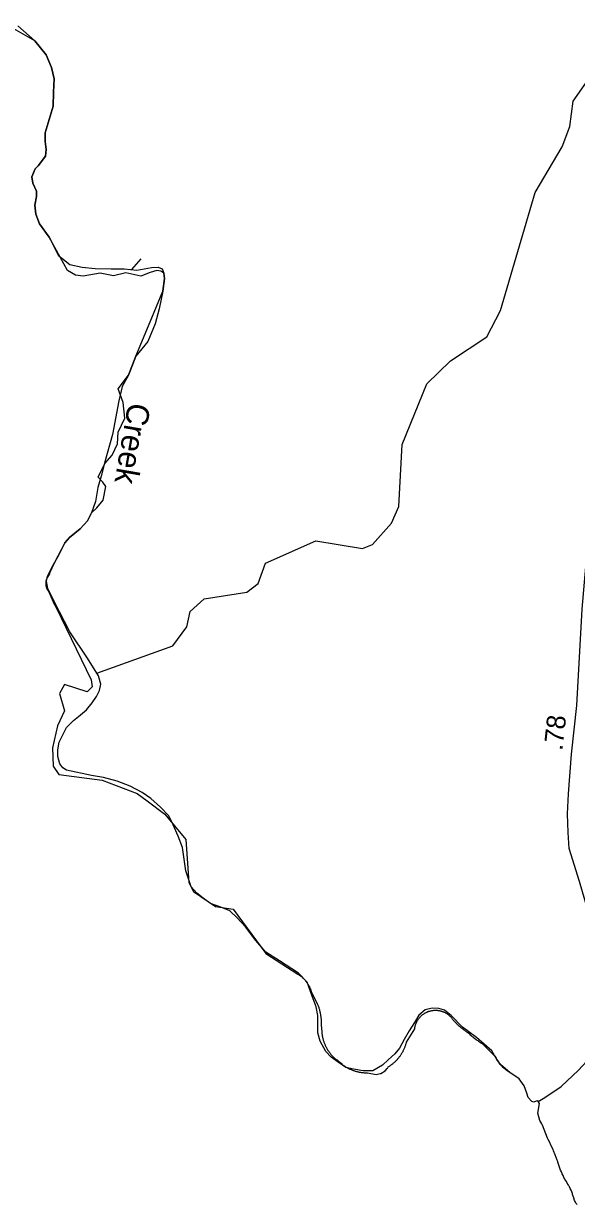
# Model space of a CAD drawing. Extents: x 2220236 to 2384410, y 720751 to 894131.
# Drawn here: x 2232586 to 2236238, y 720823 to 728622 of the extents above; entities that cross this region are included whole.
import ezdxf

# ---------------------------------------------------------------- set-up
doc = ezdxf.new("R2010")
doc.units = 0
doc.layers.add('Default', color=7, linetype='Continuous')

msp = doc.modelspace()

# ---------------------------------------------------------------- linework, layer by layer
at = {"layer": 'Default'}
for points in [[(2232770.3, 728332.6), (2232734.2, 728415.9), (2232659.3, 728507.6), (2232460.8, 728621.8)], [(2232548.3, 728607.6), (2232659.3, 728507.6), (2232734.2, 728415.9), (2232770.3, 728332.6), (2232787, 728257.6), (2232784.2, 728168.7), (2232781.4, 728077.1), (2232748.1, 727966), (2232728.7, 727899.3), (2232728.7, 727843.8), (2232735.6, 727791), (2232730.1, 727746.6), (2232682.9, 727682.7), (2232663.5, 727663.3), (2232641.3, 727610.5), (2232646.8, 727568.8), (2232671.8, 727516), (2232671.8, 727479.9), (2232660.7, 727421.6), (2232666.2, 727363.3), (2232691.2, 727299.4), (2232755.1, 727210.5), (2232816.1, 727091.1), (2232891.1, 727030), (2232973, 727013.3), (2233059, 727005), (2233164.5, 727002.2), (2233250.5, 727002.2), (2233333.8, 726993.9), (2233431, 727010.6), (2233475.4, 727013.3), (2233500.4, 727002.2), (2233511.5, 726974.4), (2233517, 726938.3), (2233505.9, 726855), (2233480.9, 726738.4), (2233456, 726638.4), (2233406, 726521.7), (2233326.9, 726424.5), (2233279.7, 726299.5), (2233238.1, 726224.5), (2233215.8, 726130.1), (2233174.2, 725907.9), (2233122.9, 725727.4), (2233097.9, 725632.9), (2233075.7, 725558), (2233061.8, 725466.3), (2233034, 725391.3), (2233009.1, 725338.5), (2232959.1, 725285.8), (2232889.7, 725227.4), (2232859.2, 725191.3)], [(2233068.9, 724331.3), (2233572.2, 724512.2), (2233663.3, 724638.2), (2233687.3, 724739.4), (2233778.3, 724822.9), (2234061.3, 724866.3), (2234135.3, 724923.8), (2234184.3, 725057.3), (2234516.3, 725204.6), (2234825.3, 725155.6), (2234891.4, 725180.6), (2235015.2, 725322.3), (2235064.2, 725432.9), (2235086.4, 725842.4), (2235249.2, 726242.5), (2235406.3, 726393.5), (2235646.4, 726552.5), (2235737.2, 726727.8), (2235964.2, 727507.1), (2236144.2, 727808.4), (2236193.3, 727941.9), (2236217.2, 728108.7), (2236439.3, 728425.5)], [(2232859.2, 725191.3), (2232889.7, 725227.4), (2232959.1, 725285.8), (2233009.1, 725338.5), (2233034, 725391.3), (2233070.2, 725422.5), (2233110.9, 725474), (2233130.2, 725564.1), (2233108.8, 725594.1), (2233078.8, 725626.3), (2233121.7, 725716.4), (2233171, 725772.2), (2233205.3, 725845.2), (2233211.8, 725922.4), (2233254.7, 726016.8), (2233244, 726119.8), (2233211.8, 726210), (2233279.7, 726299.5), (2233326.9, 726424.5), (2233422.1, 726652), (2233505.9, 726855), (2233517, 726938.3), (2233511.5, 726974.5), (2233492.9, 726986.7), (2233467.1, 726991), (2233422.1, 726978.1), (2233359.8, 726954.5), (2233261.1, 726976), (2233179.6, 726956.7), (2233091.6, 726973.8), (2232980, 726954.5), (2232928.5, 726961), (2232877.1, 726991), (2232755.1, 727210.5), (2232691.2, 727299.4), (2232666.2, 727363.3), (2232660.7, 727421.6), (2232671.8, 727479.9), (2232671.8, 727516.1), (2232646.8, 727568.8), (2232641.3, 727610.5), (2232663.5, 727663.3), (2232682.9, 727682.7), (2232730.1, 727746.6), (2232735.6, 727791), (2232728.7, 727843.8), (2232728.7, 727899.3), (2232748.1, 727966), (2232781.4, 728077.1), (2232784.2, 728168.8), (2232787, 728257.6), (2232770.3, 728332.6)], [(2233360.2, 727068.4), (2233299.2, 726997.4)], [(2235984.8, 721503.1), (2236028.2, 721528.7), (2236136.5, 721602), (2236250.8, 721708.4), (2236306.4, 721768.9), (2236361.7, 721839.3), (2236409, 721927.5), (2236442.2, 722021.8), (2236451.6, 722099.8), (2236456.9, 722193.9), (2236425.5, 722367.4), (2236349.1, 722644.7), (2236257.5, 722956.3), (2236190.6, 723173), (2236182.2, 723279.2), (2236179.1, 723403), (2236186, 723535), (2236205.8, 723797.1), (2236241.3, 724117.1), (2236276.6, 724753.6), (2236311.7, 725161.5), (2236343.5, 725365.5)], [(2232859.2, 725191.3), (2232788.9, 725058.6), (2232760.1, 724997.5), (2232755.3, 724980.6), (2232753.5, 724978.7), (2232751.9, 724976.8), (2232750.2, 724974.8), (2232748.8, 724972.8), (2232747.3, 724970.8), (2232745.7, 724968.6), (2232744.3, 724966.5), (2232743, 724964.3), (2232741.8, 724962.1), (2232740.6, 724959.7), (2232739.5, 724957.5), (2232738.5, 724955.1), (2232737.5, 724952.8), (2232736.7, 724950.4), (2232736.1, 724948), (2232735.2, 724945.5), (2232734.4, 724943), (2232734, 724940.6), (2232733.6, 724938), (2232733, 724935.5), (2232732.8, 724933), (2232732.6, 724930.4), (2232732.2, 724927.9), (2232732.2, 724925.3), (2232732.2, 724922.8), (2232732.2, 724920.3), (2232732.2, 724917.7), (2232732.6, 724915.1), (2232732.8, 724912.6), (2232733.2, 724910.1), (2232733.8, 724907.6), (2232734.2, 724905), (2232734.8, 724902.6), (2232735.4, 724900.1), (2232736.3, 724897.7), (2232737.3, 724895.3), (2232737.9, 724892.9), (2232738.9, 724890.5), (2232740.2, 724888.2), (2232741.2, 724885.9), (2232742.4, 724883.7), (2232743.6, 724881.5), (2232745.1, 724879.3), (2232746.5, 724877.2), (2232748, 724875.1), (2232749.6, 724873.1), (2232780.8, 724801.6), (2232783.4, 724796.6), (2232801.1, 724764.4), (2233032.8, 724288.2), (2233039.5, 724241.1), (2233006.5, 724208.1), (2232855.8, 724257), (2232823.8, 724196.8), (2232857, 724081.8), (2232810.1, 723983.1), (2232777.5, 723838.4), (2232780.6, 723718.1), (2232819.5, 723662.2), (2233105.8, 723624.4), (2233335.8, 723537.8), (2233401.3, 723489.3), (2233519.6, 723400.4), (2233658.2, 723233.1), (2233678.1, 722948.1), (2233708.4, 722890.3), (2233853.8, 722790.5), (2233969.4, 722773.7), (2234185.2, 722479), (2234397.8, 722343.6), (2234401.1, 722341.6), (2234404.2, 722339.4), (2234407.4, 722337.2), (2234410.7, 722335), (2234414, 722332.7), (2234417.3, 722330.3), (2234420.2, 722328), (2234423.2, 722325.4), (2234426.3, 722322.9)], [(2235989.9, 721497), (2235982, 721507.3), (2235971.8, 721505.7), (2235956.8, 721497), (2235943.9, 721502.7), (2235918.9, 721529.5), (2235910, 721558.1), (2235892.1, 721606.4), (2235860, 721652.8), (2235797.4, 721693.9), (2235736.7, 721747.6), (2235712.7, 721780.6), (2235679.4, 721836.2), (2235576.7, 721925.1), (2235485.1, 721994.5), (2235410.1, 722069.5), (2235365.7, 722105.6), (2235329.6, 722116.7), (2235285.2, 722119.5), (2235238, 722108.4), (2235196.4, 722072.3), (2235168.6, 722025.1), (2235132.5, 721969.5), (2235099.2, 721911.2), (2235068.7, 721855.6), (2235038.2, 721816.8), (2234993.7, 721777.9), (2234957.7, 721741.8), (2234892.4, 721705.7), (2234828.6, 721705.7), (2234764.7, 721716.8), (2234714.8, 721727.9), (2234664.8, 721761.2), (2234617.6, 721794.5), (2234581.5, 721833.4), (2234545.5, 721900.1), (2234528.8, 721955.6), (2234528.8, 722011.2), (2234528.8, 722069.5), (2234517.7, 722127.8), (2234492.7, 722197.3), (2234459.4, 722291.7), (2234401.1, 722350), (2234276.2, 722430.6), (2234186, 722488.9), (2234119.4, 722566.7), (2234052.7, 722655.5), (2233997.2, 722716.6), (2233947.3, 722761.1), (2233889, 722786.1), (2233819.6, 722811.1), (2233772.4, 722844.4), (2233730.8, 722877.7), (2233691.9, 722919.4), (2233675.2, 722972.2), (2233657.2, 723024.9), (2233635, 723180.5), (2233607.2, 723255.5), (2233573.9, 723330.5), (2233546.2, 723388.8), (2233490.7, 723447.1), (2233426.8, 723502.7), (2233368.5, 723544.3), (2233290.8, 723586), (2233204.7, 723619.3), (2233113.1, 723641.5), (2233035.4, 723655.4), (2232870.3, 723691.5), (2232845.3, 723705.4), (2232825.9, 723733.2), (2232812, 723780.4), (2232812, 723824.8), (2232820.3, 723874.8), (2232845.3, 723924.8), (2232870.3, 723972), (2232914.7, 724019.3), (2232948, 724044.3), (2233000.7, 724088.7), (2233039.6, 724135.9), (2233067.3, 724177.6), (2233086.8, 724216.5), (2233096.5, 724258.1), (2233079.8, 724313.7), (2233007.7, 724430.3), (2232891.1, 724605.3), (2232788.4, 724805.3), (2232746.7, 724891.4), (2232738.4, 724938.6), (2232744, 724971.9), (2232771.7, 725030.2), (2232823.1, 725119.1), (2232859.2, 725191.3)], [(2234426.3, 722322.9), (2234429.2, 722320.3), (2234432, 722317.5), (2234434.9, 722314.9), (2234437.8, 722312.1), (2234440.5, 722309.2), (2234442.9, 722306.4), (2234445.8, 722303.4), (2234448.2, 722300.4), (2234450.7, 722297.4), (2234453.2, 722294.3), (2234455.4, 722291.2), (2234457.7, 722288), (2234459.9, 722284.7), (2234462.2, 722281.5), (2234464.2, 722278.1), (2234466.3, 722274.8), (2234468.3, 722271.4), (2234470.2, 722267.9), (2234472, 722264.5), (2234473.7, 722261), (2234475.5, 722257.4), (2234477.2, 722253.9), (2234478.8, 722250.2), (2234480.2, 722246.6), (2234481.7, 722243), (2234482.9, 722239.3), (2234484.3, 722235.5), (2234485.6, 722231.8), (2234486.6, 722228), (2234528, 722143.8), (2234530.1, 722138.9), (2234531.7, 722134), (2234533.5, 722129.1), (2234535.2, 722124.2), (2234536.8, 722119.3), (2234538.3, 722114.3), (2234539.7, 722109.3), (2234540.9, 722104.3), (2234542.2, 722099.3), (2234543.6, 722094.2), (2234544.4, 722089.1), (2234545.4, 722084), (2234546.5, 722078.9), (2234547.5, 722073.8), (2234548.3, 722068.7), (2234548.9, 722063.5), (2234549.5, 722058.4), (2234550, 722053.2), (2234550.6, 722048.1), (2234551, 722042.9), (2234551.2, 722037.7), (2234551.6, 722032.5), (2234551.6, 722027.3), (2234551.6, 722022.1), (2234551.6, 722016.9), (2234551.6, 722011.8), (2234552.4, 722001.3), (2234553.2, 721990.9), (2234554.3, 721980.4), (2234555.1, 721969.9), (2234555.7, 721959.4), (2234556.5, 721948.9), (2234557.3, 721944.3), (2234557.9, 721939.7), (2234558.8, 721935.2), (2234559.8, 721930.6), (2234560.8, 721926), (2234562, 721921.5), (2234563.1, 721917), (2234564.3, 721912.5), (2234565.7, 721908), (2234567, 721903.5), (2234568.4, 721899.1), (2234570, 721894.7), (2234571.7, 721890.4), (2234573.5, 721886), (2234575.2, 721881.7), (2234577, 721877.5), (2234579.1, 721873.2), (2234580.9, 721868.9), (2234583, 721864.7), (2234585.2, 721860.6), (2234587.3, 721856.5), (2234589.5, 721852.4), (2234592, 721848.4), (2234594.2, 721844.4), (2234596.7, 721840.4), (2234599.2, 721836.5), (2234602, 721832.6), (2234604.5, 721828.8)], [(2235028.3, 721755.2), (2235031.8, 721758.3), (2235035.3, 721761.3), (2235038.6, 721764.4), (2235042.1, 721767.6), (2235045.2, 721770.9), (2235048.4, 721774.2), (2235051.7, 721777.5), (2235054.8, 721780.9), (2235058.1, 721784.4), (2235060.9, 721787.9), (2235064, 721791.5), (2235066.7, 721795.1), (2235069.8, 721798.8), (2235072.4, 721802.5), (2235075.1, 721806.2), (2235077.8, 721810), (2235080.2, 721813.9), (2235082.7, 721817.8), (2235085.3, 721821.7), (2235087.8, 721825.7), (2235090.1, 721829.7), (2235092.3, 721833.8), (2235094.2, 721837.9), (2235096.4, 721842.1), (2235098.5, 721846.2), (2235100.5, 721850.4), (2235102.2, 721854.6), (2235104, 721858.9), (2235105.8, 721863.2), (2235107.5, 721867.6), (2235108.9, 721871.9), (2235110.6, 721876.3), (2235112, 721880.7), (2235113.4, 721885.1), (2235114.7, 721889.6), (2235116.1, 721894.1), (2235169.4, 721983.1), (2235170, 721986.4), (2235170.4, 721989.6), (2235171.1, 721992.9), (2235171.7, 721996.2), (2235172.5, 721999.5), (2235173.3, 722002.7), (2235174.3, 722005.9), (2235175.2, 722009), (2235176.2, 722012.3), (2235177.4, 722015.3), (2235178.4, 722018.5), (2235179.7, 722021.6), (2235181.3, 722024.6), (2235182.7, 722027.6), (2235184.2, 722030.6), (2235185.8, 722033.5), (2235187.3, 722036.4), (2235189.1, 722039.3), (2235190.7, 722042.1), (2235192.8, 722044.9), (2235194.4, 722047.6), (2235196.5, 722050.3), (2235198.5, 722052.9), (2235200.8, 722055.5), (2235203, 722058.1), (2235205.1, 722060.5), (2235207.6, 722062.9), (2235209.8, 722065.3), (2235212.3, 722067.6), (2235214.5, 722069.9), (2235217, 722072), (2235219.7, 722074.3), (2235222.3, 722076.3), (2235225, 722078.3), (2235227.6, 722080.2), (2235230.5, 722082.1), (2235233.2, 722083.9), (2235236.1, 722085.7), (2235238.9, 722087.4), (2235241.8, 722088.9), (2235244.7, 722090.5), (2235247.7, 722091.9), (2235250.8, 722093.3), (2235254.1, 722094.7), (2235257, 722095.9), (2235260, 722097.1), (2235263.3, 722098.2), (2235266.4, 722099.2), (2235269.5, 722100.1), (2235272.8, 722101), (2235276, 722101.7), (2235279.3, 722102.4), (2235282.4, 722103.1), (2235286.1, 722103.6), (2235289.2, 722104.1), (2235292.4, 722104.5), (2235295.7, 722104.8), (2235299.2, 722105.1), (2235302.5, 722105.2), (2235305.8, 722105.3), (2235309.3, 722105.3), (2235312.5, 722105.1)], [(2235312.5, 722105.1), (2235315.8, 722105), (2235319.1, 722104.8), (2235322.6, 722104.4), (2235325.7, 722104), (2235328.9, 722103.5), (2235332.2, 722103), (2235335.5, 722102.3), (2235338.8, 722101.6), (2235342.1, 722100.8), (2235345.3, 722099.9), (2235348.4, 722098.9), (2235351.7, 722097.9), (2235354.8, 722096.8), (2235358.1, 722095.6), (2235360.9, 722094.3), (2235364, 722093), (2235367.1, 722091.6), (2235370, 722090), (2235373, 722088.5), (2235375.9, 722086.9), (2235378.8, 722085.2), (2235381.4, 722083.4), (2235384.5, 722081.6), (2235387.2, 722079.7), (2235389.8, 722077.7), (2235392.5, 722075.7), (2235395, 722073.6), (2235397.4, 722071.5), (2235400.1, 722069.2), (2235402.6, 722067), (2235405, 722064.7), (2235407.3, 722062.3), (2235410.6, 722057.8), (2235414, 722053.4), (2235417.3, 722049), (2235420.8, 722044.7), (2235424.3, 722040.4), (2235428, 722036.2), (2235431.5, 722032), (2235435.2, 722028), (2235439.1, 722023.8), (2235443, 722019.8), (2235446.8, 722015.9), (2235450.7, 722012), (2235454.8, 722008.1), (2235458.7, 722004.4), (2235463, 722000.6), (2235466.9, 721996.9), (2235471.3, 721993.4), (2235475.6, 721989.8), (2235480.1, 721986.3), (2235484.2, 721982.9), (2235488.7, 721979.6), (2235493.2, 721976.2), (2235497.7, 721973), (2235502.2, 721969.8), (2235506.7, 721966.8), (2235511.4, 721963.7), (2235516.2, 721960.8), (2235520.7, 721957.8), (2235526, 721953.1), (2235531.3, 721948.3), (2235536.5, 721943.6), (2235541.8, 721939), (2235547.3, 721934.5), (2235552.5, 721930), (2235558, 721925.5), (2235563.5, 721921.2), (2235569.3, 721916.9), (2235574.8, 721912.7), (2235580.5, 721908.5), (2235586.3, 721904.4), (2235592, 721900.4), (2235597.8, 721896.4), (2235603.7, 721892.5), (2235609.5, 721888.7), (2235615.4, 721884.9), (2235642.1, 721858.9), (2235668.3, 721832.9), (2235694.8, 721806.8), (2235698.7, 721800.8), (2235702.8, 721794.8), (2235706.7, 721788.7), (2235710.8, 721782.6), (2235714.4, 721776.4), (2235718.3, 721770.2), (2235722, 721764), (2235725.7, 721757.7), (2235730.4, 721752.1), (2235735.6, 721746.4), (2235740.5, 721740.7), (2235745.2, 721735), (2235749.9, 721729.3), (2235750.4, 721728.6)], [(2234604.5, 721828.8), (2234607.2, 721825), (2234610, 721821.3), (2234612.9, 721817.6), (2234616, 721813.9), (2234618.8, 721810.4), (2234621.9, 721806.8), (2234625, 721803.3), (2234628.3, 721799.9), (2234631.2, 721796.5), (2234634.8, 721793.2), (2234640.2, 721789.1), (2234645.7, 721785.1), (2234651.2, 721780.9), (2234656.8, 721776.6), (2234661.9, 721772.4), (2234667.2, 721768), (2234672.8, 721763.6), (2234677.7, 721759.1), (2234683, 721754.6), (2234688.2, 721750), (2234693.3, 721745.3), (2234697, 721742.6), (2234700.7, 721739.9), (2234704.6, 721737.3), (2234708.5, 721734.8), (2234712.6, 721732.3), (2234716.2, 721729.9), (2234720.4, 721727.6), (2234724.5, 721725.3), (2234728.6, 721723.2), (2234732.4, 721721), (2234736.8, 721718.9), (2234741.1, 721716.9), (2234745.2, 721715.1), (2234749.5, 721713.2), (2234753.8, 721711.5), (2234758.1, 721709.8), (2234762.2, 721708.1), (2234766.7, 721706.6), (2234771, 721705.1), (2234775.5, 721703.8), (2234780, 721702.4), (2234784.5, 721701.2), (2234789, 721700), (2234793.6, 721699), (2234798.1, 721697.9), (2234802.6, 721697), (2234807.1, 721696.1), (2234811.6, 721695.4), (2234816.3, 721694.7), (2234820.8, 721694.1), (2234825.5, 721693.5), (2234830.1, 721693.1), (2234834.8, 721692.7), (2234839.3, 721692.4), (2234844, 721692.2), (2234848.5, 721692), (2234853.2, 721691.9), (2234857.7, 721692), (2234916, 721680), (2234941.8, 721686.8), (2234946.3, 721687.9), (2234973.4, 721704), (2234988.7, 721719.9), (2234992.6, 721722.2), (2234994.3, 721731), (2235002.3, 721735.9), (2235006, 721738.5), (2235009.7, 721741.1), (2235013.6, 721743.8), (2235017.3, 721746.6), (2235021, 721749.4), (2235024.4, 721752.3), (2235028.3, 721755.2)], [(2236241.8, 720822.9), (2236236.5, 720829.5), (2236234.7, 720831.8), (2236231.8, 720836.5), (2236228.7, 720841.4), (2236225.2, 720849), (2236223.8, 720854.8), (2236221.9, 720860.5), (2236220.5, 720866.2), (2236217, 720877.6), (2236212.9, 720888.8), (2236211.1, 720894.4), (2236206.8, 720905.5), (2236202.1, 720916.4), (2236196.9, 720927.2), (2236192, 720937.9), (2236189.3, 720943.2), (2236186.3, 720948.4), (2236183.6, 720953.6), (2236177.5, 720963.9), (2236174.6, 720969), (2236171.3, 720974), (2236164.7, 720983.9), (2236161.5, 720988.9), (2236158.2, 720994.8), (2236155.3, 721000.8), (2236149.2, 721012.8), (2236143.8, 721025), (2236138.3, 721037.4), (2236133.2, 721049.8), (2236128.4, 721062.4), (2236126.2, 721068.7), (2236123.9, 721075.1), (2236122.1, 721081.4), (2236115.9, 721100.7), (2236114.3, 721107.1), (2236111, 721115.9), (2236097.7, 721150.6), (2236087, 721176.4), (2236083.3, 721184.9), (2236071.8, 721210.3), (2236059.5, 721235.3), (2236050.7, 721251.8), (2236047.1, 721261.3), (2236014.5, 721346.2), (2236009.4, 721353.9), (2235995.4, 721378), (2235982.2, 721425.9), (2235994.6, 721488.4), (2235982, 721507.3), (2235971.8, 721505.7), (2235956.8, 721497), (2235943.9, 721502.7), (2235918.9, 721529.5), (2235910, 721558.1), (2235892.1, 721606.4), (2235860, 721652.8), (2235801, 721691.6), (2235778.1, 721707.6), (2235750.4, 721728.6)]]:
    msp.add_lwpolyline(points, dxfattribs=at)

# ---------------------------------------------------------------- texts
for s, height, rotation, p in [('Creek', 150, 260.11143, (2233278.2, 726123.7)), ('.78', 125, 83.66194, (2236145.1, 723816.9))]:
    msp.add_text(s, height=height, rotation=rotation, dxfattribs=at).set_placement(p)

doc.saveas('drawing.dxf')
